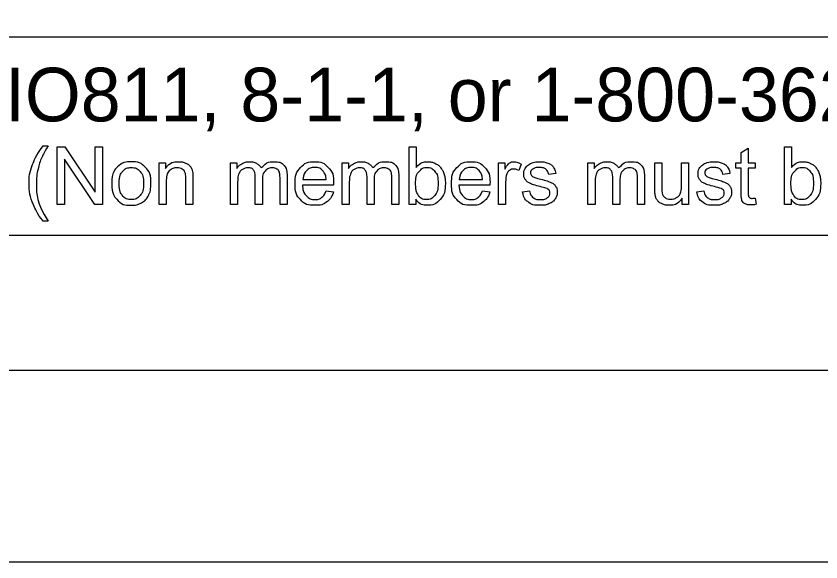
# Model space of a CAD drawing. Extents: x 0 to 43.4, y -8.1 to 22.
# Drawn here: x 13.492 to 15.591, y 0 to 1.425 of the extents above; entities that cross this region are included whole.
import ezdxf

# ---------------------------------------------------------------- set-up
doc = ezdxf.new("R2010")
doc.units = 0
for name, color, linetype in [('SH_Border', 7, 'Continuous'), ('SH_Cut_Line', 7, 'Continuous'), ('SH_Data', 7, 'Continuous'), ('SH_Text', 7, 'Continuous')]:
    doc.layers.add(name, color=color, linetype=linetype)

msp = doc.modelspace()

# ---------------------------------------------------------------- linework, layer by layer
at = {"layer": 'SH_Border'}
msp.add_lwpolyline([(1.5, 21.5), (33.5, 21.5), (33.5, 0.5), (1.5, 0.5)], close=True, dxfattribs=at)
at = {"layer": 'SH_Cut_Line'}
msp.add_lwpolyline([(0, 0), (34, 0), (34, 22), (0, 22)], close=True, dxfattribs=at)
at = {"layer": 'SH_Data'}
for p, q in [((17.3873, 1.37), (13.1373, 1.37)), ((17.3873, 0.8522), (13.1373, 0.8522))]:
    msp.add_line(p, q, dxfattribs=at)
at = {"layer": 'SH_Text'}
for points in [[(13.5619, 1.086), (13.575, 1.086)], [(13.5986, 0.9333), (13.5986, 1.0834), (13.6189, 1.0834), (13.6979, 0.9655), (13.6979, 1.0834), (13.7169, 1.0834), (13.7169, 0.9333), (13.6966, 0.9333), (13.6176, 1.0512), (13.6176, 0.9333), (13.5986, 0.9333)], [(14.5341, 0.9333), (14.517, 0.9333), (14.517, 1.0834), (14.5354, 1.0834), (14.5354, 1.0299)], [(15.383, 0.9651), (15.383, 1.0278), (15.3694, 1.0278), (15.3694, 1.0421), (15.383, 1.0421), (15.383, 1.0691), (15.4014, 1.0801), (15.4014, 1.0421), (15.4199, 1.0421), (15.4199, 1.0278), (15.4014, 1.0278), (15.4014, 0.9641)], [(15.5131, 0.9333), (15.4961, 0.9333), (15.4961, 1.0834), (15.5145, 1.0834), (15.5145, 1.0299)], [(13.8646, 0.9333), (13.8646, 1.0421), (13.8812, 1.0421), (13.8812, 1.0267)], [(14.051, 0.9333), (14.051, 1.0421), (14.0675, 1.0421), (14.0675, 1.0268)], [(14.3424, 0.9333), (14.3424, 1.0421), (14.3588, 1.0421), (14.3588, 1.0268)], [(14.7501, 0.9333), (14.7501, 1.0421), (14.7667, 1.0421), (14.7667, 1.0256)], [(14.8092, 1.0386), (14.8027, 1.0216)], [(14.9834, 0.9333), (14.9834, 1.0421), (14.9998, 1.0421), (14.9998, 1.0268)], [(15.1577, 0.9747), (15.1577, 1.0421), (15.1761, 1.0421), (15.1761, 0.9818)], [(15.2274, 0.9839), (15.2274, 1.0421), (15.2458, 1.0421), (15.2458, 0.9333), (15.2293, 0.9333)], [(14.1985, 1.008), (14.1985, 0.9333), (14.1801, 0.9333), (14.1801, 1.0018)], [(14.4899, 1.008), (14.4899, 0.9333), (14.4715, 0.9333), (14.4715, 1.0018)], [(14.8991, 1.014), (14.8811, 1.0116)], [(15.1309, 1.008), (15.1309, 0.9333), (15.1124, 0.9333), (15.1124, 1.0018)], [(15.3537, 1.014), (15.3356, 1.0116)], [(13.883, 0.9927), (13.883, 0.9333), (13.8646, 0.9333)], [(13.9529, 1.0002), (13.9529, 0.9333), (13.9345, 0.9333), (13.9345, 0.9994)], [(14.0694, 0.9897), (14.0694, 0.9333), (14.051, 0.9333)], [(14.1341, 0.9965), (14.1341, 0.9333), (14.1156, 0.9333), (14.1156, 1.0039)], [(14.2396, 0.9981), (14.3004, 0.9981)], [(14.3608, 0.9897), (14.3608, 0.9333), (14.3424, 0.9333)], [(14.4254, 0.9965), (14.4254, 0.9333), (14.407, 0.9333), (14.407, 1.0039)], [(14.6476, 0.9981), (14.7084, 0.9981)], [(14.7686, 0.9903), (14.7686, 0.9333), (14.7501, 0.9333)], [(15.0018, 0.9897), (15.0018, 0.9333), (14.9834, 0.9333)], [(15.0664, 0.9965), (15.0664, 0.9333), (15.048, 0.9333), (15.048, 1.0039)], [(14.3197, 0.983), (14.2386, 0.983)], [(14.3002, 0.9684), (14.3192, 0.966)], [(14.7277, 0.983), (14.6466, 0.983)], [(14.7082, 0.9684), (14.7272, 0.966)], [(14.8127, 0.9658), (14.8309, 0.9687)], [(15.2673, 0.9658), (15.2855, 0.9687)], [(14.5341, 0.9469), (14.5341, 0.9333)], [(15.2293, 0.9333), (15.2293, 0.9494)], [(15.4199, 0.9497), (15.4225, 0.9334)], [(15.5131, 0.9469), (15.5131, 0.9333)], [(13.575, 0.8891), (13.5619, 0.8891)]]:
    msp.add_lwpolyline(points, dxfattribs=at)
for points in [[(13.5619, 0.8891), (13.5466, 0.9084), (13.536, 0.9342), (13.5255, 0.96), (13.5255, 0.9876), (13.5255, 1.012), (13.5334, 1.0343), (13.5426, 1.0603), (13.5619, 1.086)], [(13.575, 1.086), (13.5627, 1.0647), (13.5587, 1.0555), (13.5524, 1.0414), (13.5489, 1.0261), (13.5445, 1.0069), (13.5445, 0.9875), (13.5445, 0.9383), (13.575, 0.8891)], [(13.7411, 0.9877), (13.7411, 1.0179), (13.7579, 1.0325), (13.7719, 1.0445), (13.7921, 1.0445), (13.8145, 1.0445), (13.8287, 1.0298), (13.8429, 1.0152), (13.8429, 0.9892), (13.8429, 0.9683), (13.8367, 0.9562), (13.8304, 0.9442), (13.8183, 0.9375), (13.8063, 0.9309), (13.7921, 0.9309), (13.7692, 0.9309), (13.7552, 0.9455), (13.7411, 0.9602), (13.7411, 0.9877)], [(13.7601, 0.9877), (13.7601, 0.9668), (13.7692, 0.9564), (13.7783, 0.946), (13.7921, 0.946), (13.8058, 0.946), (13.8149, 0.9565), (13.8239, 0.9669), (13.8239, 0.9883), (13.8239, 1.0085), (13.8148, 1.0189), (13.8057, 1.0293), (13.7921, 1.0293), (13.7783, 1.0293), (13.7692, 1.019), (13.7601, 1.0086), (13.7601, 0.9877)], [(13.8812, 1.0267), (13.8931, 1.0445), (13.9158, 1.0445), (13.9256, 1.0445), (13.9338, 1.041), (13.9421, 1.0375), (13.9462, 1.0317), (13.9503, 1.026), (13.9519, 1.0181), (13.9529, 1.013), (13.9529, 1.0002)], [(14.0675, 1.0268), (14.0726, 1.0348), (14.0811, 1.0397), (14.0896, 1.0445), (14.1005, 1.0445), (14.1126, 1.0445), (14.1203, 1.0395), (14.128, 1.0345), (14.1312, 1.0254), (14.1441, 1.0445), (14.1649, 1.0445), (14.1811, 1.0445), (14.1898, 1.0356), (14.1985, 1.0266), (14.1985, 1.008)], [(14.3192, 0.966), (14.3147, 0.9493), (14.3025, 0.9401), (14.2903, 0.9309), (14.2714, 0.9309), (14.2475, 0.9309), (14.2336, 0.9456), (14.2196, 0.9603), (14.2196, 0.9868), (14.2196, 1.0142), (14.2337, 1.0294), (14.2478, 1.0445), (14.2704, 1.0445), (14.2922, 1.0445), (14.306, 1.0297), (14.3198, 1.0148), (14.3198, 0.9879), (14.3198, 0.9862), (14.3197, 0.983)], [(14.3004, 0.9981), (14.2991, 1.0118), (14.2934, 1.0187), (14.2846, 1.0294), (14.2706, 1.0294), (14.2578, 1.0294), (14.2492, 1.0209), (14.2405, 1.0124), (14.2396, 0.9981)], [(14.3588, 1.0268), (14.364, 1.0348), (14.3725, 1.0397), (14.381, 1.0445), (14.3918, 1.0445), (14.4039, 1.0445), (14.4117, 1.0395), (14.4194, 1.0345), (14.4226, 1.0254), (14.4355, 1.0445), (14.4562, 1.0445), (14.4724, 1.0445), (14.4812, 1.0356), (14.4899, 1.0266), (14.4899, 1.008)], [(14.5338, 0.9885), (14.5338, 0.969), (14.5392, 0.9602), (14.5478, 0.946), (14.5627, 0.946), (14.5747, 0.946), (14.5835, 0.9565), (14.5923, 0.967), (14.5923, 0.9878), (14.5923, 1.0091), (14.5839, 1.0193), (14.5755, 1.0294), (14.5635, 1.0294), (14.5514, 1.0294), (14.5426, 1.0189), (14.5338, 1.0084), (14.5338, 0.9885)], [(14.5354, 1.0299), (14.5471, 1.0445), (14.5652, 1.0445), (14.5753, 1.0445), (14.5842, 1.0405), (14.5932, 1.0364), (14.599, 1.0291), (14.6048, 1.0218), (14.608, 1.0115), (14.6113, 1.0011), (14.6113, 0.9894), (14.6113, 0.9614), (14.5975, 0.9461), (14.5837, 0.9309), (14.5643, 0.9309), (14.545, 0.9309), (14.5341, 0.9469)], [(14.7272, 0.966), (14.7227, 0.9493), (14.7105, 0.9401), (14.6983, 0.9309), (14.6794, 0.9309), (14.6555, 0.9309), (14.6415, 0.9456), (14.6276, 0.9603), (14.6276, 0.9868), (14.6276, 1.0142), (14.6417, 1.0294), (14.6558, 1.0445), (14.6784, 1.0445), (14.7002, 1.0445), (14.714, 1.0297), (14.7278, 1.0148), (14.7278, 0.9879), (14.7278, 0.9862), (14.7277, 0.983)], [(14.7084, 0.9981), (14.7071, 1.0118), (14.7014, 1.0187), (14.6926, 1.0294), (14.6785, 1.0294), (14.6658, 1.0294), (14.6572, 1.0209), (14.6485, 1.0124), (14.6476, 0.9981)], [(14.7667, 1.0256), (14.7731, 1.0372), (14.7784, 1.0409), (14.7838, 1.0445), (14.7903, 1.0445), (14.7996, 1.0445), (14.8092, 1.0386)], [(14.8811, 1.0116), (14.8798, 1.02), (14.8739, 1.0247), (14.868, 1.0294), (14.8573, 1.0294), (14.8446, 1.0294), (14.8391, 1.0252), (14.8337, 1.021), (14.8337, 1.0154), (14.8337, 1.0118), (14.8359, 1.0089), (14.8382, 1.0059), (14.843, 1.004), (14.8458, 1.003), (14.8593, 0.9993), (14.8789, 0.994), (14.8867, 0.9907), (14.8944, 0.9874), (14.8988, 0.981), (14.9033, 0.9747), (14.9033, 0.9653), (14.9033, 0.9561), (14.8979, 0.9479), (14.8925, 0.9398), (14.8823, 0.9353), (14.8722, 0.9309), (14.8593, 0.9309), (14.8381, 0.9309), (14.827, 0.9397), (14.8158, 0.9485), (14.8127, 0.9658)], [(14.8309, 0.9687), (14.8325, 0.9577), (14.8395, 0.9518), (14.8466, 0.946), (14.8592, 0.946), (14.8719, 0.946), (14.8781, 0.9512), (14.8843, 0.9564), (14.8843, 0.9633), (14.8843, 0.9696), (14.8788, 0.9732), (14.875, 0.9756), (14.8599, 0.9794), (14.8396, 0.9846), (14.8318, 0.9883), (14.8239, 0.992), (14.8199, 0.9986), (14.8158, 1.0052), (14.8158, 1.0132), (14.8158, 1.0205), (14.8192, 1.0267), (14.8225, 1.0329), (14.8282, 1.037), (14.8326, 1.0401), (14.84, 1.0423), (14.8474, 1.0445), (14.8559, 1.0445), (14.8688, 1.0445), (14.8785, 1.0408), (14.8882, 1.0372), (14.8928, 1.0308), (14.8974, 1.0245), (14.8991, 1.014)], [(14.9998, 1.0268), (15.005, 1.0348), (15.0135, 1.0397), (15.022, 1.0445), (15.0328, 1.0445), (15.0449, 1.0445), (15.0527, 1.0395), (15.0604, 1.0345), (15.0636, 1.0254), (15.0765, 1.0445), (15.0972, 1.0445), (15.1134, 1.0445), (15.1222, 1.0356), (15.1309, 1.0266), (15.1309, 1.008)], [(15.3356, 1.0116), (15.3344, 1.02), (15.3285, 1.0247), (15.3226, 1.0294), (15.3118, 1.0294), (15.2991, 1.0294), (15.2937, 1.0252), (15.2883, 1.021), (15.2883, 1.0154), (15.2883, 1.0118), (15.2905, 1.0089), (15.2928, 1.0059), (15.2976, 1.004), (15.3004, 1.003), (15.3139, 0.9993), (15.3335, 0.994), (15.3412, 0.9907), (15.349, 0.9874), (15.3534, 0.981), (15.3578, 0.9747), (15.3578, 0.9653), (15.3578, 0.9561), (15.3524, 0.9479), (15.3471, 0.9398), (15.3369, 0.9353), (15.3267, 0.9309), (15.3139, 0.9309), (15.2927, 0.9309), (15.2815, 0.9397), (15.2704, 0.9485), (15.2673, 0.9658)], [(15.2855, 0.9687), (15.287, 0.9577), (15.2941, 0.9518), (15.3011, 0.946), (15.3138, 0.946), (15.3265, 0.946), (15.3327, 0.9512), (15.3388, 0.9564), (15.3388, 0.9633), (15.3388, 0.9696), (15.3334, 0.9732), (15.3296, 0.9756), (15.3145, 0.9794), (15.2942, 0.9846), (15.2864, 0.9883), (15.2785, 0.992), (15.2745, 0.9986), (15.2704, 1.0052), (15.2704, 1.0132), (15.2704, 1.0205), (15.2737, 1.0267), (15.2771, 1.0329), (15.2828, 1.037), (15.2871, 1.0401), (15.2946, 1.0423), (15.302, 1.0445), (15.3105, 1.0445), (15.3233, 1.0445), (15.333, 1.0408), (15.3427, 1.0372), (15.3474, 1.0308), (15.352, 1.0245), (15.3537, 1.014)], [(15.5129, 0.9885), (15.5129, 0.969), (15.5182, 0.9602), (15.5269, 0.946), (15.5417, 0.946), (15.5538, 0.946), (15.5626, 0.9565), (15.5714, 0.967), (15.5714, 0.9878), (15.5714, 1.0091), (15.563, 1.0193), (15.5545, 1.0294), (15.5426, 1.0294), (15.5305, 1.0294), (15.5217, 1.0189), (15.5129, 1.0084), (15.5129, 0.9885)], [(15.5145, 1.0299), (15.5262, 1.0445), (15.5443, 1.0445), (15.5543, 1.0445), (15.5633, 1.0405), (15.5723, 1.0364), (15.578, 1.0291), (15.5838, 1.0218), (15.5871, 1.0115), (15.5904, 1.0011), (15.5904, 0.9894), (15.5904, 0.9614), (15.5766, 0.9461), (15.5627, 0.9309), (15.5434, 0.9309), (15.5241, 0.9309), (15.5131, 0.9469)], [(13.9345, 0.9994), (13.9345, 1.0107), (13.9324, 1.0163), (13.9302, 1.0219), (13.9247, 1.0252), (13.9192, 1.0285), (13.9119, 1.0285), (13.9001, 1.0285), (13.8916, 1.021), (13.883, 1.0136), (13.883, 0.9927)], [(14.1156, 1.0039), (14.1156, 1.0162), (14.1111, 1.0224), (14.1066, 1.0285), (14.0964, 1.0285), (14.0886, 1.0285), (14.082, 1.0244), (14.0754, 1.0203), (14.0724, 1.0124), (14.0694, 1.0046), (14.0694, 0.9897)], [(14.1801, 1.0018), (14.1801, 1.0128), (14.1783, 1.0177), (14.1765, 1.0226), (14.1718, 1.0255), (14.1671, 1.0285), (14.1607, 1.0285), (14.1492, 1.0285), (14.1417, 1.0209), (14.1341, 1.0133), (14.1341, 0.9965)], [(14.407, 1.0039), (14.407, 1.0162), (14.4025, 1.0224), (14.398, 1.0285), (14.3877, 1.0285), (14.38, 1.0285), (14.3733, 1.0244), (14.3667, 1.0203), (14.3638, 1.0124), (14.3608, 1.0046), (14.3608, 0.9897)], [(14.4715, 1.0018), (14.4715, 1.0128), (14.4697, 1.0177), (14.4679, 1.0226), (14.4632, 1.0255), (14.4584, 1.0285), (14.4521, 1.0285), (14.4406, 1.0285), (14.433, 1.0209), (14.4254, 1.0133), (14.4254, 0.9965)], [(14.8027, 1.0216), (14.796, 1.0255), (14.7893, 1.0255), (14.7833, 1.0255), (14.7785, 1.0219), (14.7737, 1.0183), (14.7716, 1.0118), (14.7686, 1.002), (14.7686, 0.9903)], [(15.048, 1.0039), (15.048, 1.0162), (15.0435, 1.0224), (15.039, 1.0285), (15.0287, 1.0285), (15.021, 1.0285), (15.0143, 1.0244), (15.0077, 1.0203), (15.0048, 1.0124), (15.0018, 1.0046), (15.0018, 0.9897)], [(15.1124, 1.0018), (15.1124, 1.0128), (15.1107, 1.0177), (15.1089, 1.0226), (15.1041, 1.0255), (15.0994, 1.0285), (15.0931, 1.0285), (15.0816, 1.0285), (15.074, 1.0209), (15.0664, 1.0133), (15.0664, 0.9965)], [(14.2386, 0.983), (14.2396, 0.965), (14.2487, 0.9555), (14.2578, 0.946), (14.2715, 0.946), (14.2816, 0.946), (14.2888, 0.9513), (14.296, 0.9567), (14.3002, 0.9684)], [(14.6466, 0.983), (14.6476, 0.965), (14.6567, 0.9555), (14.6658, 0.946), (14.6795, 0.946), (14.6896, 0.946), (14.6968, 0.9513), (14.704, 0.9567), (14.7082, 0.9684)], [(15.2293, 0.9494), (15.2166, 0.9309), (15.1948, 0.9309), (15.1852, 0.9309), (15.1769, 0.9346), (15.1685, 0.9383), (15.1645, 0.9438), (15.1604, 0.9494), (15.1588, 0.9575), (15.1577, 0.963), (15.1577, 0.9747)], [(15.1761, 0.9818), (15.1761, 0.9674), (15.1772, 0.9624), (15.179, 0.9551), (15.1846, 0.9509), (15.1902, 0.9468), (15.1985, 0.9468), (15.2068, 0.9468), (15.2141, 0.951), (15.2213, 0.9553), (15.2244, 0.9626), (15.2274, 0.9699), (15.2274, 0.9839)], [(15.4225, 0.9334), (15.4147, 0.9318), (15.4086, 0.9318), (15.3986, 0.9318), (15.393, 0.935), (15.3875, 0.9382), (15.3853, 0.9433), (15.383, 0.9485), (15.383, 0.9651)], [(15.4014, 0.9641), (15.4014, 0.9562), (15.4024, 0.9539), (15.4034, 0.9516), (15.4056, 0.9503), (15.4078, 0.949), (15.4118, 0.949), (15.4149, 0.949), (15.4199, 0.9497)]]:
    msp.add_open_spline(points, degree=3, dxfattribs=at)

# ---------------------------------------------------------------- texts
msp.add_text('OHIO811, 8-1-1, or 1-800-362-2764', height=0.14, dxfattribs=at).set_placement((13.1817, 1.15))

doc.saveas('drawing.dxf')
